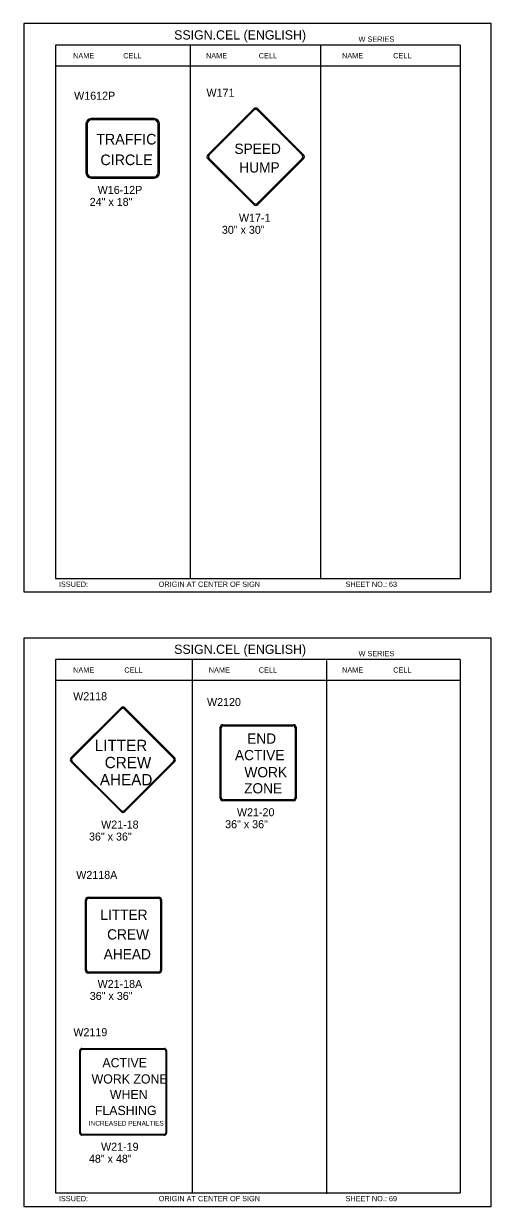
# Model space of a CAD drawing. Extents: x -5299 to 22597, y -19549 to -1808.
# Drawn here: x 1769 to 2470, y -8230 to -6456 of the extents above; entities that cross this region are included whole.
import ezdxf

# ---------------------------------------------------------------- set-up
doc = ezdxf.new("R2010")
doc.units = 0
for name, color, linetype in [('Level 1', 7, 'Continuous'), ('Level 2', 7, 'Continuous'), ('Level 3', 7, 'Continuous'), ('Level 62', 7, 'Continuous')]:
    doc.layers.add(name, color=color, linetype=linetype)

msp = doc.modelspace()

# ---------------------------------------------------------------- linework, layer by layer
at = {"layer": 'Level 1'}
for p, q in [((2423.7, -6488.6), (1816.7, -6488.6)), ((1816.7, -6488.6), (1816.7, -7288.6)), ((2019, -6488.6), (2019, -7288.6)), ((2214.2, -6488.6), (2214.2, -7288.6)), ((2423.7, -6488.6), (2423.7, -7288.6)), ((2423.7, -6520.3), (1816.7, -6520.3)), ((2045.2, -6652.9), (2114, -6584.2)), ((2047.2, -6653.2), (2114.2, -6586.2)), ((2119.7, -6586.2), (2186.7, -6653.2)), ((2120, -6584.2), (2188.7, -6652.9)), ((1862.6, -6606.9), (1862.6, -6679.9)), ((1864.6, -6606.9), (1864.6, -6679.9)), ((1964.7, -6598.9), (1870.6, -6598.9)), ((1964.7, -6600.9), (1870.6, -6600.9)), ((1970.7, -6679.9), (1970.7, -6606.9)), ((1972.7, -6679.9), (1972.7, -6606.9)), ((1917.6, -6643.5), (1917.6, -6643.5)), ((2114, -6727.6), (2045.2, -6658.9)), ((2114.2, -6725.7), (2047.2, -6658.7)), ((2117.4, -6655.7), (2117.4, -6655.7)), ((2186.7, -6658.7), (2119.7, -6725.7)), ((2188.7, -6658.9), (2120, -6727.6)), ((1870.6, -6685.9), (1964.7, -6685.9)), ((1870.6, -6687.9), (1964.7, -6687.9)), ((1816.7, -7288.6), (2423.7, -7288.6)), ((2423.7, -7410), (1816.7, -7410)), ((1816.7, -7410), (1816.7, -8210)), ((2021.6, -7409.6), (2021.6, -8209.6)), ((2222.9, -7411.5), (2222.9, -8211.5)), ((2423.7, -7410), (2423.7, -8210)), ((2423.7, -7441.7), (1816.7, -7441.7)), ((1840.1, -7557.7), (1915.2, -7482.6)), ((1841.9, -7557.9), (1915.4, -7484.3)), ((1920.4, -7484.3), (1993.9, -7557.9)), ((1920.6, -7482.6), (1995.7, -7557.7)), ((2063.8, -7618), (2063.8, -7511.7)), ((2065.2, -7616.9), (2065.2, -7512.9)), ((2067.6, -7507.9), (2173.9, -7507.9)), ((2068.7, -7509.4), (2172.7, -7509.4)), ((2176.2, -7512.9), (2176.2, -7616.9)), ((2177.6, -7511.7), (2177.6, -7618)), ((1915.2, -7638.2), (1840.1, -7563.1)), ((1915.4, -7636.4), (1841.9, -7562.8)), ((1917.8, -7560.2), (1917.8, -7560.2)), ((1993.9, -7562.8), (1920.4, -7636.4)), ((1995.7, -7563.1), (1920.6, -7638.2)), ((2120.7, -7564.9), (2120.7, -7564.9)), ((2173.9, -7621.8), (2067.6, -7621.8)), ((2172.7, -7620.4), (2068.7, -7620.4)), ((1865.8, -7766.6), (1972, -7766.6)), ((1866.9, -7768), (1970.9, -7768)), ((1862, -7876.7), (1862, -7770.4)), ((1863.4, -7875.5), (1863.4, -7771.5)), ((1974.4, -7771.5), (1974.4, -7875.5)), ((1975.8, -7770.4), (1975.8, -7876.7)), ((1918.9, -7823.5), (1918.9, -7823.5)), ((1972, -7880.4), (1865.8, -7880.4)), ((1970.9, -7879), (1866.9, -7879)), ((1853.4, -8120.2), (1853.4, -7996.6)), ((1854.6, -8119.2), (1854.6, -7997.5)), ((1856.6, -7993.3), (1980.2, -7993.3)), ((1857.6, -7994.5), (1979.3, -7994.5)), ((1982.3, -7997.5), (1982.3, -8119.2)), ((1983.5, -7996.6), (1983.5, -8120.2)), ((1918.4, -8058.4), (1918.4, -8058.4)), ((1980.2, -8123.4), (1856.6, -8123.4)), ((1979.3, -8122.2), (1857.6, -8122.2)), ((1816.7, -8210), (2423.7, -8210))]:
    msp.add_line(p, q, dxfattribs=at)
for centre, radius, start, end in [((2117, -6587.2), 4.23, 45, 135), ((2117, -6588.9), 3.87, 45, 135), ((1870.6, -6606.9), 8, 90, 180), ((1870.6, -6606.9), 6, 90, 180), ((1964.7, -6606.9), 8, 0, 90), ((1964.7, -6606.9), 6, 0, 90), ((2048.2, -6655.9), 4.23, 135, 225), ((2050, -6655.9), 3.87, 135, 225), ((2184, -6655.9), 3.87, 315, 45), ((2185.7, -6655.9), 4.23, 315, 45), ((1870.6, -6679.9), 8, 180, 270), ((1870.6, -6679.9), 6, 180, 270), ((1964.7, -6679.9), 6, 270, 0), ((1964.7, -6679.9), 8, 270, 0), ((2117, -6724.7), 4.23, 225, 315), ((2117, -6722.9), 3.87, 225, 315), ((1917.9, -7485.2), 3.8, 45, 135), ((1917.9, -7486.8), 3.48, 45, 135), ((2067.6, -7511.7), 3.8, 90, 180), ((2068.7, -7512.9), 3.48, 90, 180), ((2172.7, -7512.9), 3.48, 0, 90), ((2173.9, -7511.7), 3.8, 0, 90), ((1842.8, -7560.4), 3.8, 135, 225), ((1844.3, -7560.4), 3.48, 135, 225), ((1991.5, -7560.4), 3.48, 315, 45), ((1993, -7560.4), 3.8, 315, 45), ((2067.6, -7618), 3.8, 180, 270), ((2068.7, -7616.9), 3.48, 180, 270), ((2172.7, -7616.9), 3.48, 270, 0), ((2173.9, -7618), 3.8, 270, 0), ((1917.9, -7635.5), 3.8, 225, 315), ((1917.9, -7634), 3.48, 225, 315), ((1865.8, -7770.4), 3.8, 90, 180), ((1866.9, -7771.5), 3.48, 90, 180), ((1970.9, -7771.5), 3.48, 0, 90), ((1972, -7770.4), 3.8, 0, 90), ((1866.9, -7875.5), 3.48, 180, 270), ((1970.9, -7875.5), 3.48, 270, 0), ((1865.8, -7876.7), 3.8, 180, 270), ((1972, -7876.7), 3.8, 270, 0), ((1856.6, -7996.6), 3.25, 90, 180), ((1857.6, -7997.5), 2.98, 90, 180), ((1979.3, -7997.5), 2.98, 0, 90), ((1980.2, -7996.6), 3.25, 0, 90), ((1856.6, -8120.2), 3.25, 180, 270), ((1857.6, -8119.2), 2.98, 180, 270), ((1979.3, -8119.2), 2.98, 270, 0), ((1980.2, -8120.2), 3.25, 270, 0)]:
    msp.add_arc(centre, radius, start, end, dxfattribs=at)
at = {"layer": 'Level 62'}
for points in [[(1769.2, -7308.8), (2470.2, -7308.8), (2470.2, -6456.4), (1769.2, -6456.4)], [(1769.2, -8230.2), (2470.2, -8230.2), (2470.2, -7377.8), (1769.2, -7377.8)]]:
    msp.add_lwpolyline(points, close=True, dxfattribs=at)

# ---------------------------------------------------------------- texts
at = {"layer": 'Level 1'}
for s, height, p in [('TRAFFIC', 16, (1877.9, -6637.7)), ('SPEED', 15.36, (2085.1, -6651.7)), ('CIRCLE', 16, (1884.2, -6668.6)), ('HUMP', 15.36, (2092.4, -6679.7)), ('LITTER', 17.08, (1875.8, -7547.5)), ('END', 15.37, (2104.2, -7536.3)), ('CREW', 17.08, (1890.7, -7573.1)), ('ACTIVE', 15.37, (2085.9, -7561.1)), ('WORK', 15.37, (2100.1, -7586.7)), ('AHEAD', 17.08, (1883.4, -7598.8)), ('ZONE', 15.37, (2099.6, -7610.9)), ('LITTER', 15.37, (1884.1, -7800.6)), ('CREW', 15.37, (1894.3, -7830)), ('AHEAD', 15.37, (1889.1, -7859.7)), ('ACTIVE', 13.83, (1887.2, -8021.7)), ('WORK ZONE', 13.83, (1871, -8046)), ('WHEN', 13.83, (1898.4, -8069.3)), ('FLASHING', 13.83, (1875.9, -8093.3)), ('INCREASED PENALTIES', 7, (1866.9, -8109.1))]:
    msp.add_text(s, height=height, dxfattribs=at).set_placement(p)
at = {"layer": 'Level 2'}
for s, p in [('W1612P', (1844.8, -6570.5)), ('W171', (2043.2, -6566)), ('W2118', (1843.4, -7471.1)), ('W2120', (2044, -7479.8)), ('W2118A', (1848, -7739.1)), ('W2119', (1843.7, -7975))]:
    msp.add_text(s, height=12, dxfattribs=at).set_placement(p)
at = {"layer": 'Level 3'}
for s, height, p in [('SSIGN.CEL (ENGLISH)', 13.857, (1994.8, -6480.2)), ('W SERIES', 7.92, (2271.2, -6483.6)), ('NAME', 7.92, (1843.3, -6508.4)), ('CELL', 7.92, (1918.5, -6508.4)), ('NAME', 7.92, (2042.6, -6508.4)), ('CELL', 7.92, (2121.6, -6508.4)), ('NAME', 7.92, (2246.5, -6508.4)), ('CELL', 7.92, (2323.1, -6508.4)), ('W16-12P', 12, (1880.1, -6711.7)), ('24" x 18"', 12, (1868.2, -6729.7)), ('W17-1', 12, (2091.9, -6753.6)), ('30" x 30"', 12, (2066.3, -6771.6)), ('ISSUED:', 7.92, (1822, -7301.1)), ('ORIGIN AT CENTER OF SIGN', 7.918, (1971.6, -7301.1)), ('SHEET NO.: 63', 7.918, (2251.7, -7301.1)), ('SSIGN.CEL (ENGLISH)', 13.857, (1994.8, -7401.6)), ('W SERIES', 7.92, (2271.2, -7405.1)), ('NAME', 7.92, (1843.3, -7429.8)), ('CELL', 7.92, (1920.1, -7429.8)), ('NAME', 7.92, (2046.7, -7429.8)), ('CELL', 7.92, (2121.6, -7429.8)), ('NAME', 7.92, (2246.5, -7429.8)), ('CELL', 7.92, (2323.1, -7429.8)), ('W21-20', 12, (2088.9, -7645.1)), ('W21-18', 12, (1885.3, -7663.6)), ('36" x 36"', 12, (2071.2, -7663.1)), ('36" x 36"', 12, (1867.1, -7681.6)), ('W21-18A', 12, (1880, -7902.6)), ('36" x 36"', 12, (1868.3, -7920.6)), ('W21-19', 12, (1885.2, -8146.8)), ('48" x 48"', 12, (1867, -8164.8)), ('ISSUED:', 7.92, (1822, -8222.5)), ('ORIGIN AT CENTER OF SIGN', 7.918, (1971.6, -8222.5)), ('SHEET NO.: 69', 7.918, (2251.7, -8222.5))]:
    msp.add_text(s, height=height, dxfattribs=at).set_placement(p)

doc.saveas('drawing.dxf')
